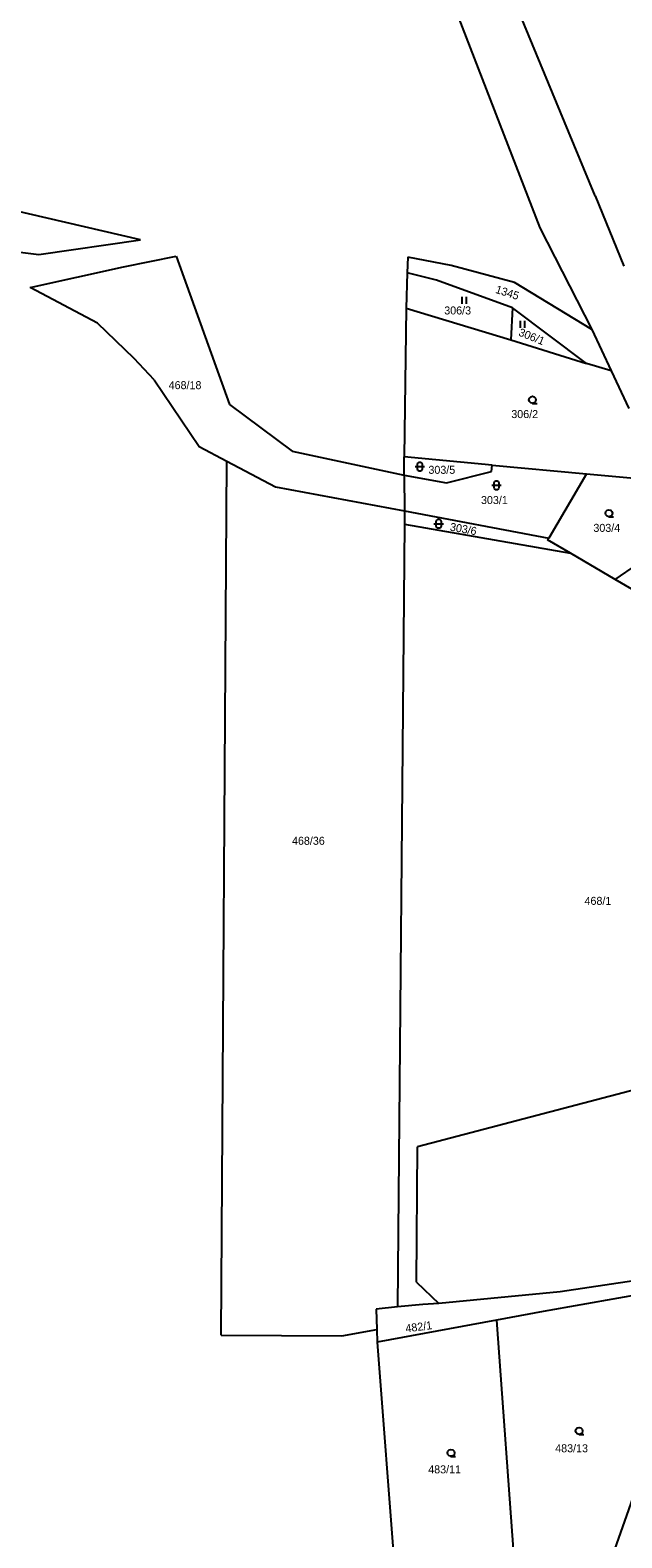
# Model space of a CAD drawing. Extents: x -852001 to -842497, y -1063614 to -1052182.
# Drawn here: x -844799.8 to -844674.2, y -1061526.1 to -1061205.9 of the extents above; entities that cross this region are included whole.
import ezdxf

# ---------------------------------------------------------------- set-up
doc = ezdxf.new("R2010")
doc.units = 0
for name, color, linetype in [('Default', 7, 'Continuous'), ('KN_HRANICE', 7, 'Continuous'), ('KN_KULTURY', 7, 'Continuous'), ('KN_PARCELY', 7, 'Continuous')]:
    doc.layers.add(name, color=color, linetype=linetype)

# ---------------------------------------------------------------- blocks, each defined once
blk = doc.blocks.new('304')
at = {"layer": 'Default'}
blk.add_lwpolyline([(0, 0), (-0.38, 0.1), (-0.65, 0.37), (-0.75, 0.74), (-0.65, 1.11), (-0.38, 1.38), (-0.01, 1.48), (0.36, 1.38), (0.63, 1.11), (0.73, 0.73), (0.63, 0.35), (0.36, 0.08), (-0.02, -0.02), (0.98, -0.02)], dxfattribs=at)
blk = doc.blocks.new('306')
at = {"layer": 'Default'}
for p, q in [((-0.5, 1.5), (-0.5, 0)), ((0.5, 0), (0.5, 1.5))]:
    blk.add_line(p, q, dxfattribs=at)
blk = doc.blocks.new('316')
at = {"layer": 'Default'}
for points in [[(-1, 1), (0.27, 1), (1, 1)], [(-0.5, 1.5), (-0.4, 1.79), (-0.15, 1.97), (0.16, 1.97), (0.41, 1.79), (0.51, 1.5), (0.51, 0.5), (0.41, 0.21), (0.16, 0.03), (-0.15, 0.03), (-0.4, 0.21), (-0.5, 0.5), (-0.5, 1.5)]]:
    blk.add_lwpolyline(points, dxfattribs=at)

msp = doc.modelspace()

# ---------------------------------------------------------------- linework, layer by layer
at = {"layer": 'KN_HRANICE'}
for p, q in [((-844720.73, -1061172.52), (-844691.6, -1061247.89)), ((-844685.56, -1061227.38), (-844703.99, -1061182.85)), ((-844679.88, -1061241.1), (-844685.56, -1061227.38)), ((-844679.88, -1061241.1), (-844673.82, -1061256.03)), ((-844776.42, -1061250.39), (-844804.1, -1061244)), ((-844852.01, -1061247.02), (-844797.97, -1061253.52)), ((-844691.6, -1061247.89), (-844680.59, -1061269.45)), ((-844797.97, -1061253.52), (-844776.42, -1061250.39)), ((-844780.02, -1061256.12), (-844768.84, -1061253.9)), ((-844768.84, -1061253.9), (-844757.5, -1061285.36)), ((-844719.67, -1061254.09), (-844719.77, -1061257.41)), ((-844710.46, -1061255.86), (-844719.67, -1061254.09)), ((-844799.79, -1061260.56), (-844780.02, -1061256.12)), ((-844719.77, -1061257.41), (-844719.98, -1061264.93)), ((-844713.56, -1061258.96), (-844719.77, -1061257.41)), ((-844697.02, -1061259.49), (-844710.46, -1061255.86)), ((-844785.52, -1061268.09), (-844799.79, -1061260.56)), ((-844697.4, -1061264.85), (-844713.56, -1061258.96)), ((-844680.59, -1061269.45), (-844697.02, -1061259.49)), ((-844719.98, -1061264.93), (-844720.4, -1061296.53)), ((-844719.98, -1061264.93), (-844697.8, -1061271.68)), ((-844697.4, -1061264.85), (-844697.8, -1061271.68)), ((-844681.7, -1061276.68), (-844697.4, -1061264.85)), ((-844777.71, -1061275.61), (-844785.52, -1061268.09)), ((-844680.59, -1061269.45), (-844676.52, -1061278.21)), ((-844697.8, -1061271.68), (-844681.7, -1061276.68)), ((-844773.47, -1061280.17), (-844777.71, -1061275.61)), ((-844676.52, -1061278.21), (-844681.7, -1061276.68)), ((-844773.47, -1061280.17), (-844763.91, -1061294.34)), ((-844676.52, -1061278.21), (-844672.78, -1061286.23)), ((-844757.5, -1061285.36), (-844744.19, -1061295.34)), ((-844763.91, -1061294.34), (-844758.07, -1061297.42)), ((-844744.19, -1061295.34), (-844720.45, -1061300.43)), ((-844720.45, -1061300.43), (-844720.4, -1061296.53)), ((-844701.72, -1061298.26), (-844720.4, -1061296.53)), ((-844759.29, -1061483.09), (-844758.07, -1061297.42)), ((-844758.07, -1061297.42), (-844747.75, -1061302.86)), ((-844711.43, -1061302.02), (-844701.87, -1061299.6)), ((-844701.87, -1061299.6), (-844701.72, -1061298.26)), ((-844701.72, -1061298.26), (-844681.7, -1061300.12)), ((-844747.75, -1061302.86), (-844720.38, -1061308)), ((-844720.45, -1061300.43), (-844711.43, -1061302.02)), ((-844720.45, -1061300.43), (-844720.38, -1061308)), ((-844681.7, -1061300.12), (-844689.75, -1061313.76)), ((-844681.7, -1061300.12), (-844664.39, -1061301.73)), ((-844720.38, -1061308), (-844720.36, -1061310.83)), ((-844720.38, -1061308), (-844689.75, -1061313.76)), ((-844720.36, -1061310.83), (-844721.83, -1061477.08)), ((-844720.36, -1061310.83), (-844685.12, -1061317)), ((-844689.75, -1061313.76), (-844689.98, -1061314.15)), ((-844685.12, -1061317), (-844689.98, -1061314.15)), ((-844675.67, -1061322.54), (-844685.12, -1061317)), ((-844675.67, -1061322.54), (-844670.88, -1061319.31)), ((-844669.9, -1061325.92), (-844675.67, -1061322.54)), ((-844580.08, -1061406.78), (-844717.62, -1061443.09)), ((-844717.8, -1061471.84), (-844717.62, -1061443.09)), ((-844717.8, -1061471.84), (-844713.04, -1061476.31)), ((-844660.03, -1061472.53), (-844690.91, -1061478.06)), ((-844660.74, -1061469.85), (-844687.29, -1061473.84)), ((-844687.29, -1061473.84), (-844713.04, -1061476.31)), ((-844721.83, -1061477.08), (-844726.34, -1061477.54)), ((-844726.34, -1061477.54), (-844726.21, -1061481.89)), ((-844716.45, -1061476.54), (-844721.83, -1061477.08)), ((-844713.04, -1061476.31), (-844716.45, -1061476.54)), ((-844690.91, -1061478.06), (-844700.84, -1061479.9)), ((-844733.65, -1061483.23), (-844726.21, -1061481.89)), ((-844726.21, -1061481.89), (-844726.14, -1061484.58)), ((-844700.84, -1061479.9), (-844726.14, -1061484.58)), ((-844700.84, -1061479.9), (-844695.93, -1061547.63)), ((-844759.29, -1061483.09), (-844733.65, -1061483.23)), ((-844726.14, -1061484.58), (-844721.31, -1061547.47)), ((-844676.11, -1061529.78), (-844669.25, -1061510.34))]:
    msp.add_line(p, q, dxfattribs=at)

# ---------------------------------------------------------------- block references
at = {"layer": 'KN_KULTURY'}
for name, p in [('306', (-844707.69, -1061264.01)), ('306', (-844695.34, -1061269.11)), ('304', (-844693.19, -1061285.14)), ('316', (-844717.11, -1061299.59)), ('316', (-844700.84, -1061303.55)), ('304', (-844676.96, -1061309.22)), ('316', (-844713.11, -1061311.72)), ('304', (-844683.3, -1061504.13)), ('304', (-844710.48, -1061508.8))]:
    msp.add_blockref(name, p, dxfattribs=at)

# ---------------------------------------------------------------- texts
at = {"layer": 'KN_PARCELY'}
for s, rotation, p in [('1345', 342.228, (-844701.19, -1061261.66)), ('306/1', 338.045, (-844696.31, -1061270.7)), ('303/6', 349.733, (-844710.81, -1061312.16)), ('482/1', 7.334, (-844720.04, -1061482.49))]:
    msp.add_text(s, height=1.7, rotation=rotation, dxfattribs=at).set_placement(p)
for s, p in [('306/3', (-844711.92, -1061266.27)), ('468/18', (-844770.41, -1061282.14)), ('306/2', (-844697.69, -1061288.28)), ('303/5', (-844715.28, -1061300.12)), ('303/1', (-844704.12, -1061306.54)), ('303/4', (-844680.27, -1061312.45)), ('468/36', (-844744.23, -1061378.91)), ('468/1', (-844682.15, -1061391.67)), ('483/13', (-844688.37, -1061507.94)), ('483/11', (-844715.32, -1061512.42))]:
    msp.add_text(s, height=1.7, dxfattribs=at).set_placement(p)

doc.saveas('drawing.dxf')
